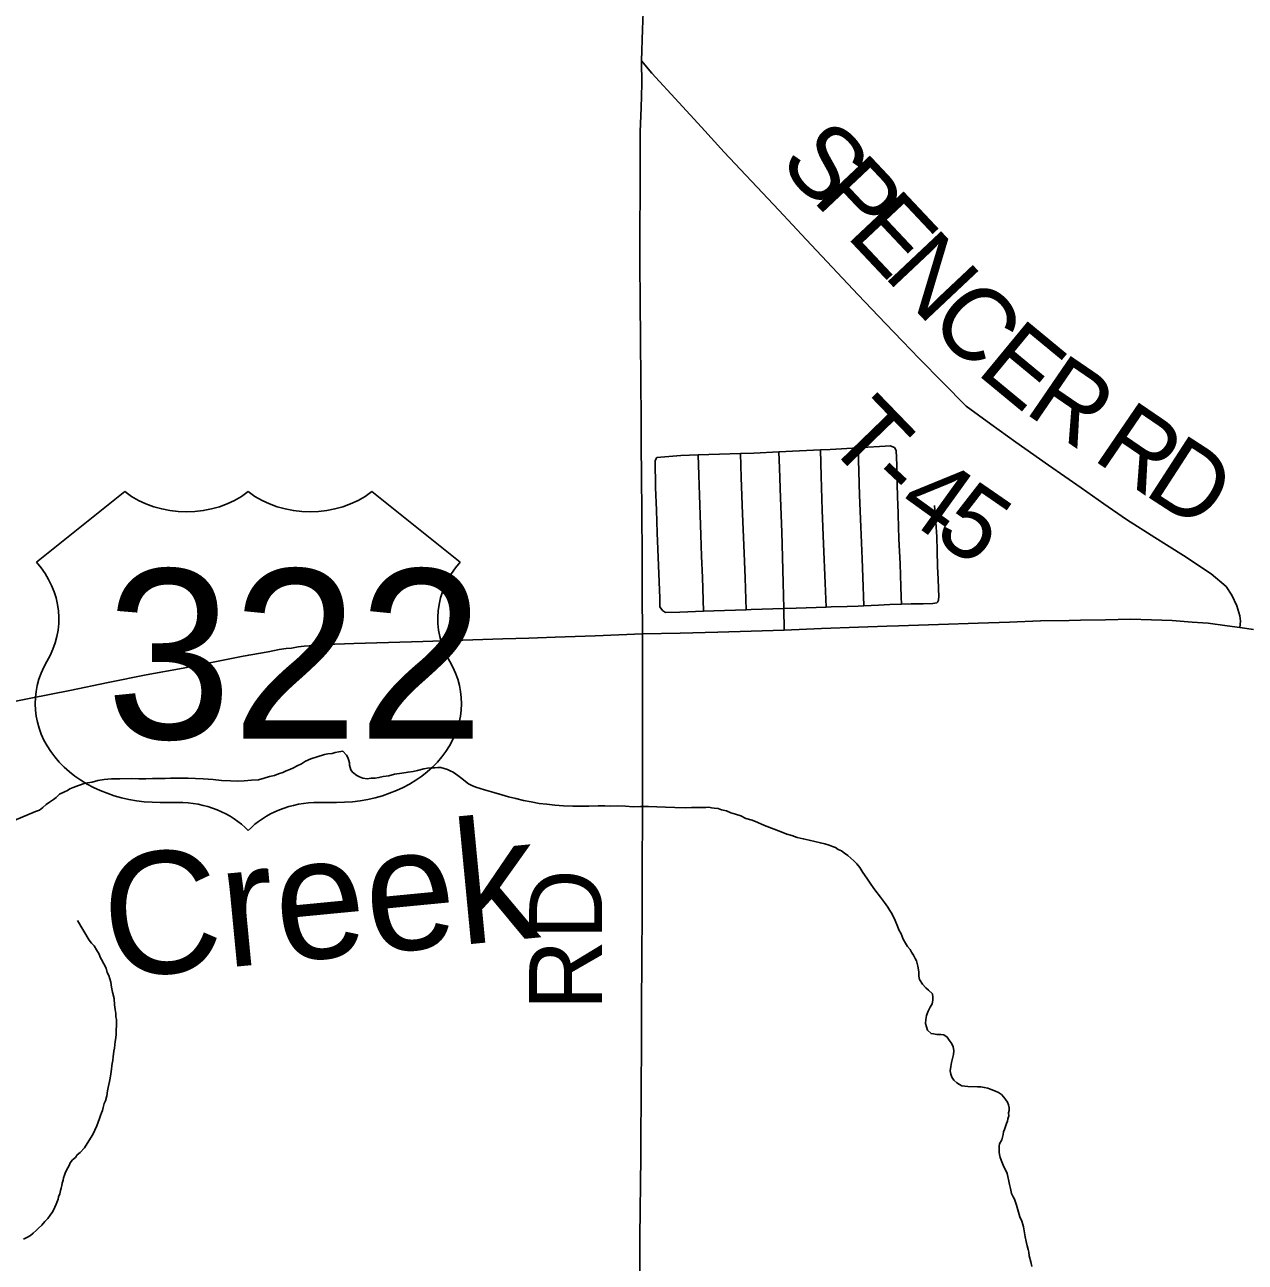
# Model space of a CAD drawing. Extents: x 103424 to 290657, y 38711 to 110967.
# Drawn here: x 149253 to 154300, y 81314 to 86428 of the extents above; entities that cross this region are included whole.
import ezdxf

# ---------------------------------------------------------------- set-up
doc = ezdxf.new("R2010")
doc.units = 0
for name, color, linetype in [('GM_X_County_Road', 7, 'Continuous'), ('GM_X_County_Road_Text', 7, 'Continuous'), ('GM_X_Minor_River', 7, 'Continuous'), ('GM_X_Minor_River_Text', 7, 'Continuous'), ('GM_X_Township_Road', 7, 'Continuous'), ('GM_X_Township_Road_Text', 7, 'Continuous'), ('GM_X_US_Location', 7, 'Continuous'), ('GM_X_US_Route', 7, 'Continuous'), ('GM_X_US_Shield', 7, 'Continuous')]:
    doc.layers.add(name, color=color, linetype=linetype)

msp = doc.modelspace()

# ---------------------------------------------------------------- linework, layer by layer
at = {"layer": 'GM_X_County_Road'}
msp.add_line((151807, 83220.5), (151808.1, 83910.7), dxfattribs=at)
for points in [[(151803.6, 86279.8), (151807.8, 86408.6), (151811.3, 86515.8)], [(151808.1, 83910.7), (151806.9, 84075.7), (151805.7, 84240.8), (151804.5, 84405.9), (151803.2, 84570.9), (151802.4, 84683.2), (151801.5, 84795.4), (151800.3, 84960.5), (151799, 85125.6), (151797.8, 85285.2), (151796.6, 85444.9), (151797.4, 85877), (151798.5, 85987.2), (151801.6, 86085.4), (151804.7, 86183.7), (151803.6, 86279.8)], [(151795.4, 81212.9), (151796.3, 81315.9), (151797.2, 81418.9), (151798.2, 81528.8), (151799.3, 81638.7), (151800.1, 81749.9), (151800.8, 81861.1), (151801.6, 81965.7), (151802.3, 82070.2), (151802.9, 82177.4), (151803.4, 82284.5), (151803.9, 82407.1), (151804.4, 82529.8), (151805.6, 82802.9), (151806.4, 82891.4), (151807, 83220.5)]]:
    msp.add_lwpolyline(points, dxfattribs=at)
at = {"layer": 'GM_X_Minor_River'}
for points in [[(149157.9, 83117.8), (149298.1, 83176.9), (149314.1, 83183.2), (149328, 83193.6), (149341.9, 83205.9), (149355.9, 83216.3), (149371.8, 83226.7), (149383.8, 83235), (149397.6, 83249.4), (149417.7, 83257.8), (149429.7, 83264.1), (149439.6, 83270.3), (149453.6, 83276.6), (149475.7, 83285.1), (149503.8, 83293.7), (149532, 83298.3), (149556.1, 83304.7), (149582.2, 83309.2), (149612.4, 83311.8), (149646.7, 83312.4), (149693.1, 83313.3), (149725.4, 83311.8), (149753.7, 83312.3), (149781.9, 83312.8), (149810.1, 83313.4), (149834.3, 83313.8), (149856.5, 83314.2), (149878.7, 83314.6), (149902.9, 83315), (149929.1, 83315.5), (149959.4, 83314), (149991.7, 83312.6), (150032.2, 83309.3), (150066.5, 83305.8), (150104.9, 83304.5), (150135.2, 83303), (150161.4, 83303.5), (150191.6, 83306.1), (150219.8, 83308.6), (150243.9, 83315.1), (150266, 83321.5), (150286.1, 83325.9), (150302.1, 83332.3), (150320.2, 83338.7), (150334.2, 83345), (150350.2, 83351.3), (150364.2, 83357.6), (150380.2, 83366), (150398.2, 83374.4), (150414.2, 83384.8), (150436.2, 83395.3), (150492.4, 83412.5), (150506.4, 83414.8), (150524.6, 83417.1), (150536.6, 83421.4), (150552.7, 83423.7), (150568.8, 83426), (150583.2, 83410.1), (150589.4, 83400.1), (150593.7, 83388), (150595.9, 83378), (150596.1, 83367.9), (150602.4, 83349.8), (150608.7, 83339.8), (150627.1, 83326), (150637.3, 83320.1), (150651.5, 83314.3), (150669.7, 83312.6), (150685.8, 83315), (150701.9, 83315.2), (150718, 83317.5), (150736.1, 83321.9), (150758.3, 83324.3), (150782.4, 83330.8), (150812.5, 83335.4), (150838.7, 83339.9), (150858.8, 83342.3), (150876.9, 83346.7), (150903, 83353.2), (150919.1, 83355.5), (150933.2, 83357.8), (150949.4, 83358.1), (150961.4, 83358.3), (150973.6, 83358.5), (150987.8, 83354.7), (151001.9, 83350.9), (151012.1, 83345.1), (151024.3, 83339.2), (151034.5, 83333.3), (151044.8, 83325.4), (151055, 83317.5), (151087.7, 83291.9), (151102, 83284), (151118.2, 83278.3), (151136.5, 83272.5), (151154.8, 83266.8), (151173, 83261.1), (151193.3, 83255.4), (151225.8, 83245.9), (151254.2, 83238.3), (151284.6, 83230.8)], [(151284.6, 83230.8), (151315, 83223.2), (151347.3, 83217.7), (151379.8, 83210.2), (151412.1, 83206.8), (151444.5, 83203.3), (151480.8, 83199.9), (151519.2, 83198.6), (151553.5, 83199.2), (151585.7, 83199.8), (151624.1, 83200.5), (151652.3, 83201), (151676.6, 83199.4), (151704.8, 83199.9), (151737.1, 83198.5), (151769.4, 83197), (151799.7, 83197.6), (151832, 83198.2), (151866.3, 83196.8), (151902.6, 83195.4), (151941, 83194.1), (151983.4, 83192.8), (152009.6, 83193.3), (152027.8, 83193.6), (152037.8, 83193.8), (152047.9, 83194), (152060, 83194.2), (152070.1, 83194.3), (152082.2, 83194.6), (152092.3, 83192.7), (152104.5, 83190.9), (152120.6, 83189.2), (152134.9, 83183.4), (152155.1, 83179.7), (152173.4, 83172), (152191.7, 83166.2), (152214, 83158.6), (152234.4, 83148.8), (152260.7, 83141.2), (152285.1, 83131.5), (152311.6, 83119.9), (152380.6, 83092.9), (152405, 83083.2), (152425.3, 83077.5), (152447.6, 83069.8), (152472, 83064.2), (152496.3, 83058.6), (152520.6, 83052.9), (152542.9, 83047.3), (152561.1, 83043.6), (152579.4, 83037.8), (152593.6, 83032), (152605.8, 83028.2), (152616, 83020.3), (152630.2, 83014.5), (152642.5, 83004.6), (152656.8, 82994.8), (152669.1, 82984.9), (152681.4, 82973), (152693.7, 82961.1), (152706.1, 82945.2), (152718.6, 82925.2), (152735.2, 82901.2), (152751.7, 82877.3), (152768.3, 82853.4), (152791, 82823.5), (152807.6, 82801.5), (152822.1, 82781.6), (152830.4, 82767.6), (152838.7, 82755.6), (152842.9, 82745.6), (152849.1, 82733.6), (152855.4, 82719.6), (152861.8, 82703.5), (152868.1, 82687.5), (152876.5, 82671.5), (152884.9, 82649.4), (152895.3, 82633.4), (152903.6, 82619.4), (152914, 82607.5), (152920.2, 82595.5), (152928.5, 82583.5), (152934.8, 82569.5), (152941, 82559.5), (152945.5, 82537.3), (152949.9, 82515.2), (152950.2, 82497), (152952.5, 82482.9), (152965, 82463), (152979.3, 82449.1), (152989.6, 82439.1), (153006, 82423.3), (153008.3, 82409.2), (153008.5, 82397.1), (153004.7, 82382.9), (152996.9, 82368.6), (152989.1, 82352.3), (152981.4, 82334), (152979.7, 82317.8), (152977.9, 82301.6), (152982.2, 82287.5)], [(149472.3, 82726.6), (149519.4, 82645.5), (149529.7, 82633.6), (149540, 82621.6), (149550.4, 82605.7), (149560.8, 82587.7), (149565.1, 82575.6), (149571.3, 82565.6), (149590.1, 82529.6), (149594.5, 82511.5), (149600.7, 82499.5), (149605, 82485.4), (149609.3, 82471.4), (149611.7, 82451.2), (149616.1, 82431.1), (149622.6, 82404.9), (149625.1, 82378.7), (149627.5, 82358.6), (149629.8, 82342.4), (149630, 82328.3), (149632.2, 82318.2), (149632.4, 82306.1), (149632.7, 82292), (149631, 82275.8), (149631.3, 82257.6), (149629.6, 82241.4), (149627.8, 82227.3), (149626, 82213.1), (149624.3, 82198.9), (149622.5, 82186.8), (149620.7, 82174.6), (149618.8, 82164.5), (149617.1, 82148.3), (149615.3, 82136.1), (149613.5, 82126), (149611.7, 82111.8), (149610, 82093.6), (149606.3, 82075.3), (149604.6, 82061.2), (149600.7, 82049), (149598.9, 82036.8), (149595.2, 82022.6), (149593.5, 82002.4), (149587.8, 81982.1), (149582, 81969.9), (149578.2, 81953.6), (149574.4, 81941.5), (149570.6, 81931.3), (149566.7, 81921.1), (149562.9, 81908.9), (149557.1, 81892.7), (149551.3, 81878.4), (149543.6, 81860.1), (149537.8, 81847.9), (149531.9, 81837.7), (149500.5, 81786.6), (149482.7, 81768.1), (149470.8, 81757.8), (149462.9, 81747.5), (149451, 81737.2), (149441.1, 81724.9), (149437.2, 81714.7), (149431.4, 81704.5), (149421.6, 81686.2), (149417.8, 81674), (149413.9, 81663.8), (149412.1, 81653.7), (149408.3, 81641.5), (149406.4, 81631.4), (149404.6, 81621.2), (149400.8, 81611.1), (149399, 81596.9), (149393.2, 81584.7), (149391.3, 81574.5), (149383.6, 81554.2), (149377.8, 81542), (149370, 81523.6), (149358.2, 81509.3), (149348.3, 81495), (149336.5, 81482.6), (149324.6, 81468.3), (149310.7, 81455.9), (149300.8, 81445.6), (149288.9, 81435.3), (149277, 81425), (149265, 81418.7), (149249, 81410.4)], [(152982.2, 82287.5), (152986.5, 82273.4), (153000.9, 82259.6), (153011, 82257.7), (153025.2, 82256), (153041.3, 82256.2), (153053.4, 82254.4), (153067.7, 82244.6), (153076, 82232.6), (153084.3, 82220.7), (153092.6, 82206.7), (153095, 82188.5), (153093.2, 82172.3), (153089.5, 82156.1), (153085.8, 82139.9), (153082, 82123.6), (153080.3, 82105.4), (153082.6, 82091.3), (153086.8, 82079.3), (153095.1, 82067.3), (153107.4, 82055.4), (153117.6, 82049.5), (153127.8, 82043.7), (153140, 82041.9), (153152.1, 82040.1), (153192.5, 82038.8), (153206.6, 82039), (153220.8, 82037.2), (153235, 82033.5), (153249.2, 82027.7), (153267.4, 82021.9), (153279.7, 82016.1), (153291.9, 82008.2), (153302.2, 81996.3), (153310.5, 81986.3), (153316.7, 81976.3), (153320.9, 81964.3), (153323.2, 81952.2), (153323.4, 81942.1), (153321.5, 81932), (153321.7, 81919.9), (153317.9, 81907.7), (153316.1, 81897.5), (153312.2, 81887.4), (153308.4, 81875.2), (153304.6, 81863), (153300.7, 81852.8), (153298.9, 81842.7), (153293.2, 81820.4), (153283.5, 81804), (153281.6, 81793.9), (153281.8, 81781.8), (153282, 81769.7), (153284.2, 81759.6), (153286.5, 81747.5), (153292.9, 81729.5), (153301.3, 81709.4), (153309.6, 81693.4), (153315.9, 81681.4), (153318.1, 81669.3), (153322.5, 81649.2), (153324.8, 81635.1), (153329.1, 81619), (153333.5, 81598.9), (153339.8, 81584.8), (153346.1, 81574.9), (153350.3, 81562.8), (153354.6, 81550.8), (153359, 81530.6), (153367.5, 81502.5), (153375.9, 81484.5), (153380.2, 81470.4), (153382.4, 81460.4), (153389.2, 81420.1), (153393.6, 81400), (153397.9, 81381.8), (153402.2, 81367.8), (153404.5, 81355.7), (153406.7, 81341.6), (153413.3, 81315.5), (153417.6, 81297.4)]]:
    msp.add_lwpolyline(points, dxfattribs=at)
at = {"layer": 'GM_X_Township_Road'}
msp.add_line((153020.6, 84373.3), (153015.1, 84441.5), dxfattribs=at)
for points in [[(151803.6, 86279.8), (151846.9, 86228.5), (151958.3, 86106.7), (152051.7, 86004.4), (152145.3, 85902.1), (152258.3, 85781.8), (152371.3, 85661.5), (152484.4, 85541.2), (152591.6, 85427), (152698.9, 85312.8), (152812.9, 85193.4), (152882.2, 85120.9), (152951.4, 85048.4), (153048.8, 84949.9), (153146.2, 84851.4), (153248.5, 84777.1), (153350.7, 84702.7), (153486.2, 84608.4), (153621.6, 84514.1), (153715, 84449.1), (153808.3, 84384.1), (153926.4, 84309.9), (154044.4, 84235.6), (154159, 84159.7), (154221.1, 84106.2), (154243.7, 84070.7), (154264.3, 84026.4), (154276.7, 83985.9), (154279.4, 83963.8), (154277.7, 83937.9)], [(151866.4, 84639.6), (151966.1, 84647.8), (152037.8, 84650.3), (152125.4, 84653.3), (152213, 84656.3), (152267.9, 84658.1), (152370.9, 84663), (152457.1, 84667), (152543.3, 84671.1), (152583.1, 84672.9), (152698.9, 84679.9), (152716, 84680.9), (152810.7, 84686.6), (152831.6, 84687.6), (152850.2, 84680.7)], [(151890, 84007.5), (151879.9, 84022.4), (151879.2, 84059), (151874, 84193.5), (151868.8, 84328), (151865.2, 84422), (151861.6, 84516), (151859.9, 84627.5), (151866.4, 84639.6)], [(152060.4, 84004.5), (152055.4, 84144.6), (152052.1, 84232.3), (152048.7, 84319.8), (152043.3, 84484.8), (152040.6, 84567.6), (152037.8, 84650.3)], [(152236.6, 84010.8), (152231.7, 84143.3), (152226.7, 84277.4), (152221.5, 84406.7), (152216, 84557.1), (152213, 84656.3)], [(152394, 83927.1), (152392.2, 84015.5), (152388.2, 84175.9), (152383.6, 84330.9), (152377.6, 84473.8), (152374.4, 84595.5), (152370.9, 84663)], [(152566.4, 84021.7), (152562.4, 84121.2), (152555.5, 84282.8), (152550.7, 84421.7), (152546.1, 84562.6), (152543.3, 84671.1)], [(152722.7, 84026.8), (152719, 84144.9), (152715.8, 84221.9), (152710.3, 84353.2), (152704.8, 84484.5), (152701.9, 84582.2), (152698.9, 84679.9)], [(152878.1, 84034.1), (152876.8, 84064.5), (152876.3, 84106.6), (152872.6, 84200.6), (152868.1, 84303.5), (152864.7, 84402.5), (152862.9, 84451.2), (152862.2, 84470.9), (152860.4, 84538.1), (152858.5, 84610.2), (152856.7, 84668.7), (152850.2, 84680.7)], [(153029.3, 84045.4), (153030.9, 84050.3), (153031.6, 84055.3), (153032.2, 84062.8), (153029.4, 84137.5), (153027.9, 84189.6), (153026.2, 84254.5), (153024.4, 84312.4), (153020.6, 84373.3)], [(151890, 84007.5), (151902.3, 83998.9), (151962, 84000.4), (152060.4, 84004.5), (152102.2, 84006.2), (152236.6, 84010.8), (152256.3, 84011.4), (152392.2, 84015.5), (152443.3, 84016.9), (152566.4, 84021.7), (152587.3, 84022.5), (152653.7, 84024), (152699.3, 84025.7), (152722.7, 84026.8), (152783.4, 84029.7), (152829.7, 84032.1), (152878.1, 84034.1), (152918.8, 84035.1), (152968.4, 84035.7), (153007.8, 84036.4), (153024, 84039.6), (153027.5, 84042.5), (153029.3, 84045.4)]]:
    msp.add_lwpolyline(points, dxfattribs=at)
at = {"layer": 'GM_X_US_Route'}
for points in [[(153571.9, 83966.7), (153618.3, 83967.7), (153721.9, 83969.8), (153825.6, 83971.9), (153911.6, 83969.4), (153997.7, 83967), (154079.7, 83960), (154146.6, 83955.2), (154224.9, 83944.9), (154277.7, 83937.9)], [(149162.9, 83621.7), (149278.4, 83644.9), (149440.2, 83677.6), (149597.8, 83709.6), (149755.4, 83741.5), (149909.2, 83769.5), (150033, 83794.4), (150156.8, 83819.2), (150259.4, 83837), (150305.2, 83846.2), (150333.8, 83850.5), (150357, 83852.6), (150384, 83857), (150408.3, 83859.7), (150429.4, 83861.8), (150452.5, 83863.4), (150496.8, 83866.7), (150613.9, 83871.5), (150756.9, 83875.5), (150899.9, 83879.6), (151064.8, 83884.8), (151229.8, 83890), (151338.1, 83893.5), (151446.5, 83896.9), (151611.4, 83903.2), (151709.8, 83906.9), (151808.1, 83910.7), (151963.5, 83914.6), (152118.8, 83918.5), (152256.4, 83922.8), (152394, 83927.1), (152547.5, 83932.8), (152701, 83938.4), (152818.1, 83942.5)], [(152818.1, 83942.5), (152866, 83944.1), (153031, 83949.8), (153195.9, 83955.5), (153324.6, 83959.9), (153453.2, 83964.4), (153571.9, 83966.7)], [(154277.7, 83937.9), (154334, 83929.3)]]:
    msp.add_lwpolyline(points, dxfattribs=at)
at = {"layer": 'GM_X_US_Shield'}
for p, q in [((149667.1, 84498.9), (149302.3, 84207.1)), ((151053.4, 84207.1), (150688.6, 84498.9)), ((149813.1, 83214.8), (149886, 83214.8)), ((150469.7, 83214.8), (150542.7, 83214.8))]:
    msp.add_line(p, q, dxfattribs=at)
for centre, major_axis, start_param, end_param in [((149922.5, 84707.4), (-364.8, 0), 0.795399, 2.346194), ((150433.2, 84707.4), (-364.8, 0), 0.795399, 2.346194), ((148884, 83972.7), (510.7, 0), 5.838949, 6.894067), ((151471.8, 83972.7), (-510.7, 0), 5.672304, 6.727422), ((149807.4, 83623.4), (510.7, 0), 2.702327, 4.723529), ((150548.4, 83623.4), (-510.7, 0), 1.559657, 3.580859), ((149886, 82923), (-364.8, 0), 3.785094, 4.712389), ((150469.7, 82923), (-364.8, 0), 4.712389, 5.639684)]:
    msp.add_ellipse(centre, major_axis=major_axis, ratio=0.8, start_param=start_param, end_param=end_param, dxfattribs=at)

# ---------------------------------------------------------------- texts
at = {"layer": 'GM_X_County_Road_Text'}
msp.add_text('RD', height=301.87, rotation=90, dxfattribs=at).set_placement((151640.8, 82355.6))
at = {"layer": 'GM_X_Minor_River_Text'}
msp.add_text('Creek', height=503.42, rotation=5.4979, dxfattribs=at).set_placement((149601.2, 82485.4))
at = {"layer": 'GM_X_Township_Road_Text'}
for s, rotation, p in [('S', 313.2694, (152365.5, 85853.2)), ('P', 313.2661, (152505.1, 85704.9)), ('E', 313.2716, (152644.7, 85556.6)), ('N', 313.261, (152799.5, 85392.2)), ('C', 313.4575, (152982.3, 85197.9)), ('E', 320.4639, (153182.3, 84990.5)), ('R', 325.6354, (153380.2, 84828.9)), ('T', 314.0818, (152555.5, 84706.4)), ('R', 325.6942, (153662.3, 84635.7)), ('D', 327.075, (153873.7, 84491.5)), ('-', 316.8836, (152724.1, 84532.9)), ('4', 324.2269, (152847.2, 84421.4)), ('5', 325.3847, (153003.5, 84308.9))]:
    msp.add_text(s, height=301.9, rotation=rotation, dxfattribs=at).set_placement(p)
at = {"layer": 'GM_X_US_Location'}
for s, p in [('0', (150178.4, 83827.2)), ('/', (150178.5, 83827.2))]:
    msp.add_text(s, height=1.01, dxfattribs=at).set_placement(p)
msp.add_text('322', height=1.01, rotation=0, dxfattribs=at).set_placement((149868.9, 83618.9))
at = {"layer": 'GM_X_US_Shield'}
msp.add_text('322', height=700.44, dxfattribs=at).set_placement((149589.2, 83477.5))

doc.saveas('drawing.dxf')
